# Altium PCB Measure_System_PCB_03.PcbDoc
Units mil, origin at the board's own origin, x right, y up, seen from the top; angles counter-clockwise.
Board outline 6000 x 4000 mil, 2 copper layers (Top Layer, Bottom Layer); 42 components, 34 nets, 113 pads, 0 vias.
Unrouted connection lines stored in the file: 1.
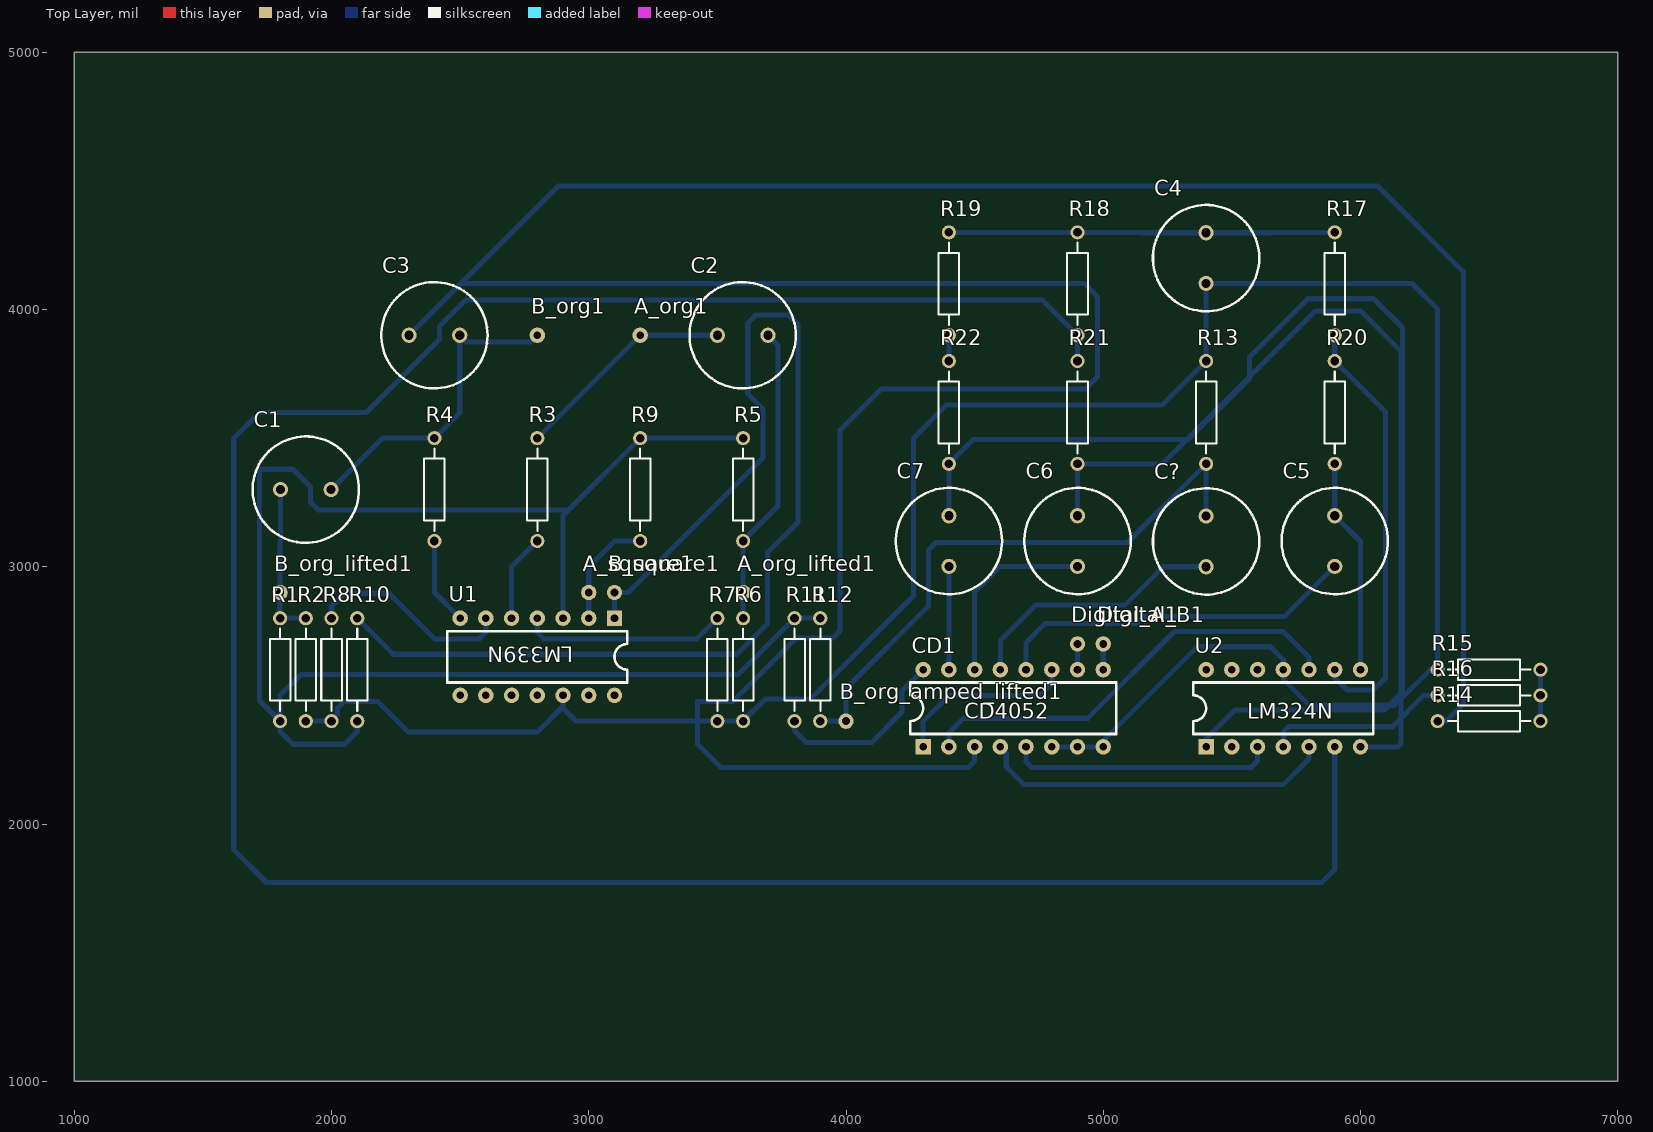
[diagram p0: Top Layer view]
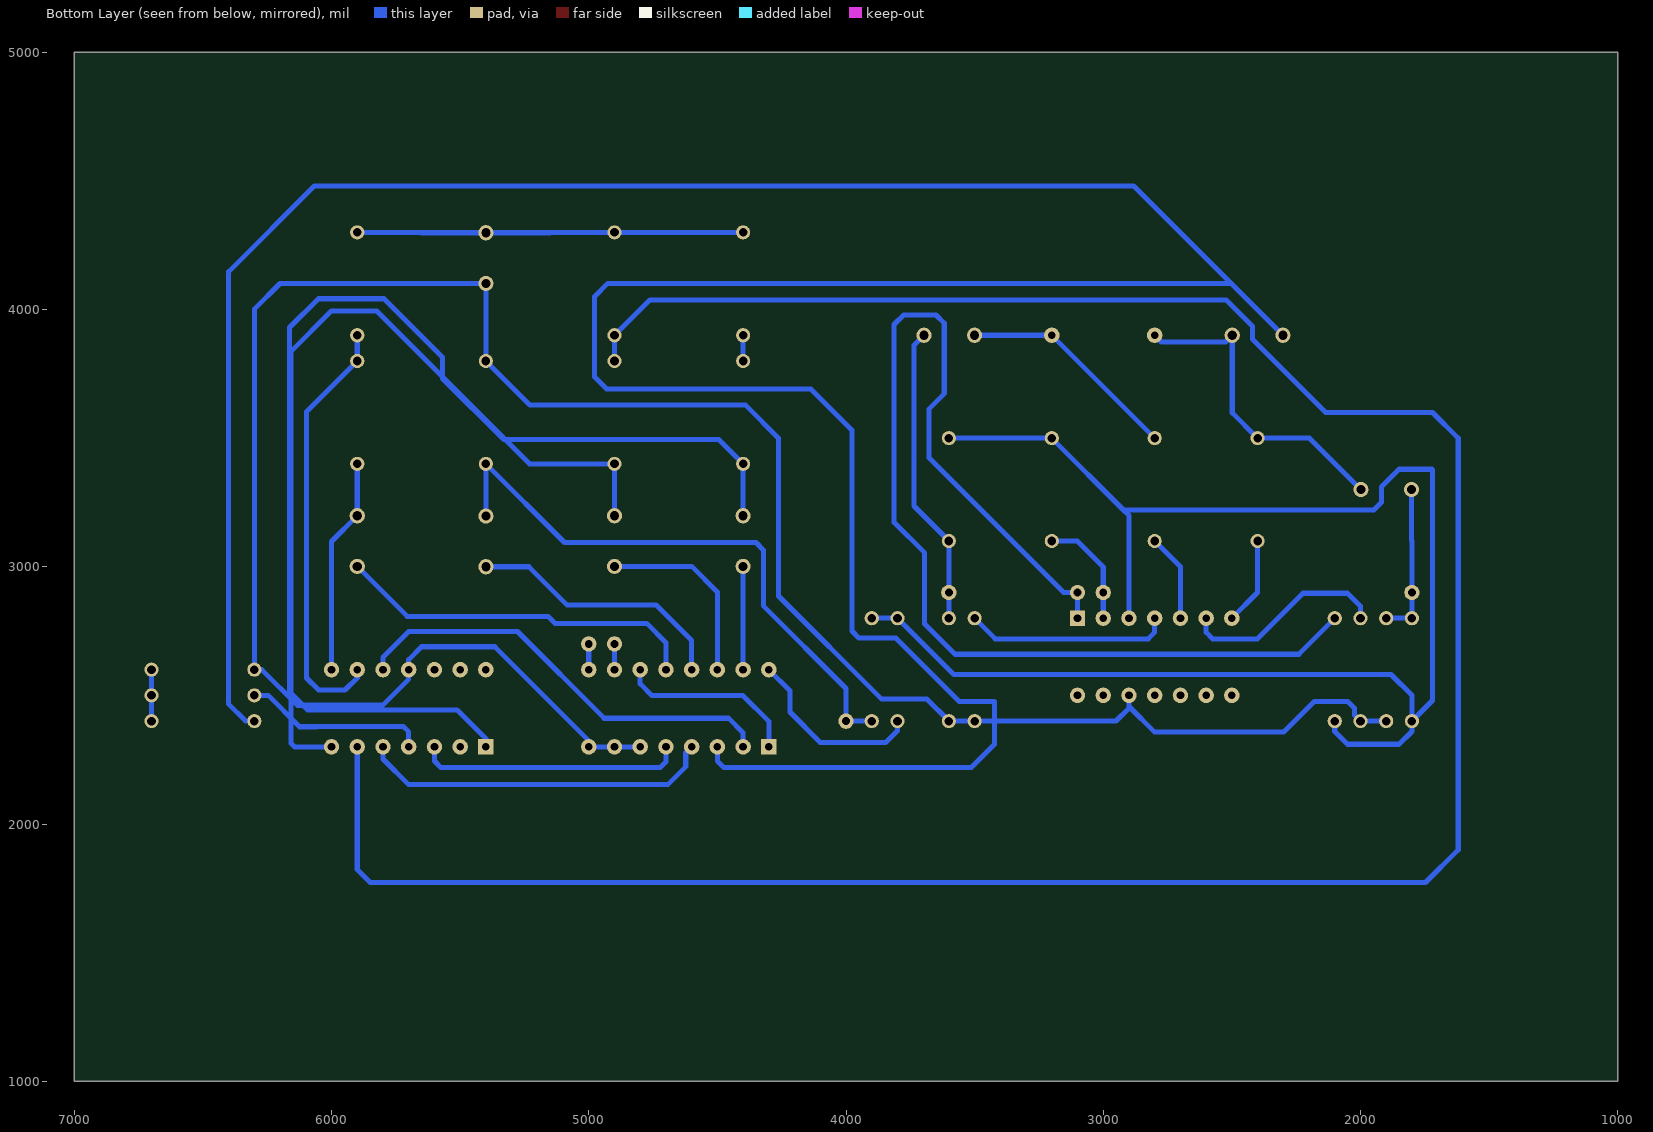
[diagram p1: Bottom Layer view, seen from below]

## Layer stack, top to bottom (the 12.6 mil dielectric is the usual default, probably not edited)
Top Solder: solder mask 0.4, Solder Resist, Dk 3.5
Top Layer: signal copper 1.4
Dielectric 1: dielectric 12.6, FR-4, Dk 4.8
Bottom Layer: signal copper 1.4
Bottom Solder: solder mask 0.4, Solder Resist, Dk 3.5

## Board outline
1000,1000 7000,1000 7000,5000 1000,5000

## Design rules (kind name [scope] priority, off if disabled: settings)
Clearance [All] p1: gap=39.37 ignorepadtopadclearanceinfootprint=FALSE
PolygonConnect [All] p1: connectstyle=Relief reliefconductorwidth=10 reliefentries=4 polygonreliefangle="90 Angle" airgapwidth=10
RoutingLayers [All] p1: top layer_v5=FALSE bottom layer_v5=TRUE
RoutingVias [All] p1: holewidth=28 width=50 viastyle="Through Hole" minholewidth=28 minwidth=50 maxholewidth=28 maxwidth=50
SolderMaskExpansion [All] p1: expansion=4 istentingtop=FALSE
Width [All] p1: maxlimit=393.7 minlimit=19.68 preferedwidth=19.68
29 further rules are at their usual default settings.

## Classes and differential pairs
component class Part_Square: C1 C2 R1 R2 R3 R4 R5 R6 R7 R8 R9 R10 U1
component class Part_PGA: C3 C4 C5 C6 C7 C? CD1 R11 R12 R13 R14 R15 R16 R17 R18 R19 R20 R21 R22 U2
component class Measure_System_Main: A_org1 A_org_lifted1 A_square1 B_org1 B_org_amped_lifted1 B_org_lifted1 B_square1 Digital_A1 Digital_B1

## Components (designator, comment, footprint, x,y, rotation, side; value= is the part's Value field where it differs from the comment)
A_org1 "Hole" Hole 3200,3900 r90 top
A_org_lifted1 "Hole" Hole 3600,2900 r90 top
A_square1 "Hole" Hole 3000,2900 r90 top
B_org1 "Hole" Hole 2800,3900 r90 top
B_org_amped_lifted1 "Hole" Hole 4000,2400 r270 top
B_org_lifted1 "Hole" Hole 1800,2900 r90 top
B_square1 "Hole" Hole 3100,2900 r90 top
C1 "Cap Pol1" RB5-10.5 1900,3300 r180 top value=10u
C2 "Cap Pol1" RB5-10.5 3598.43,3900 r0 top value=10u
C3 "Cap Pol1" RB5-10.5 2400,3900 r180 top value=10u
C4 "Cap Pol1" RB5-10.5 5400,4200 r90 top value=10u
C5 "Cap Pol1" RB5-10.5 5900,3100 r270 top value=10u
C6 "Cap Pol1" RB5-10.5 4900,3100 r270 top value=10u
C7 "Cap Pol1" RB5-10.5 4400,3100 r270 top value=10u
C? "Cap Pol1" RB5-10.5 5400,3098.43 r90 top value=10u
CD1 "CD4052" CD4052 4300,2300 r90 top
Digital_A1 "Hole" Hole 4900,2700 r90 top
Digital_B1 "Hole" Hole 5000,2700 r90 top
R1 "Res2" AXIAL-0.4 1800,2600 r270 top value=100k
R2 "Res2" AXIAL-0.4 1900,2600 r90 top value=100k
R3 "Res2" AXIAL-0.4 2800,3300 r90 top value=1k
R4 "Res2" AXIAL-0.4 2400,3300 r90 top value=1k
R5 "Res2" AXIAL-0.4 3600,3300 r90 top value=100k
R6 "Res2" AXIAL-0.4 3600,2600 r90 top value=100k
R7 "Res2" AXIAL-0.4 3500,2600 r90 top value=10k
R8 "Res2" AXIAL-0.4 2000,2600 r270 top value=10k
R9 "Res2" AXIAL-0.4 3200,3300 r270 top value=10k
R10 "Res2" AXIAL-0.4 2100,2600 r270 top value=10k
R11 "Res2" AXIAL-0.4 3800,2600 r90 top value=200
R12 "Res2" AXIAL-0.4 3900,2600 r90 top value=100k
R13 "Res2" AXIAL-0.4 5400,3600 r270 top value=100k
R14 "Res2" AXIAL-0.4 6500,2400 r180 top value=100k
R15 "Res2" AXIAL-0.4 6500,2600 r0 top value=100k
R16 "Res2" AXIAL-0.4 6500,2500 r0 top value=100k
R17 "Res2" AXIAL-0.4 5900,4100 r270 top value=50k
R18 "Res2" AXIAL-0.4 4900,4100 r270 top value=24k
R19 "Res2" AXIAL-0.4 4400,4100 r270 top value=12k
R20 "Res2" AXIAL-0.4 5900,3600 r270 top value=100k
R21 "Res2" AXIAL-0.4 4900,3600 r270 top value=100k
R22 "Res2" AXIAL-0.4 4400,3600 r270 top value=100k
U1 "LM339N" LM339N 3100,2800 r270 top
U2 "LM324N" LM324N 5400,2300 r90 top

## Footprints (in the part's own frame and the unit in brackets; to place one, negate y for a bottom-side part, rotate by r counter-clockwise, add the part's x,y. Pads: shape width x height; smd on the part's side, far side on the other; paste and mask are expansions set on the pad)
AXIAL-0.4 [mm] "Axial Device, Thru-Hole; 2 Leads; 0.4 in Pin Spacing"
  round 1.4 hole 0.85: 1(-5.08,0) 2(5.08,0)
  silkscreen extent -4.06,-1.02 4.06,1.02
CD4052 [mil]
  rect 60x60 hole 30: 1(0,0)
  round 60 hole 30 mask+4: 2(0,-100) 3(0,-200) 4(0,-300) 5(0,-400) 6(0,-500) 7(0,-600) 8(0,-700) 9(300,-700) 10(300,-600) 11(300,-500) 12(300,-400) 13(300,-300) 14(300,-200) 15(300,-100) 16(300,0)
  silkscreen extent 50,-750 250,50
Hole [mil]
  round 60 hole 30 mask+4: 1(0,0)
LM324N [mil]
  rect 60x60 hole 30: 1(0,0)
  round 60 hole 30 mask+4: 2(0,-100) 3(0,-200) 4(0,-300) 5(0,-400) 6(0,-500) 7(0,-600) 8(300,-600) 9(300,-500) 10(300,-400) 11(300,-300) 12(300,-200) 13(300,-100) 14(300,0)
  silkscreen extent 50,-650 250,50
LM339N [mil]
  rect 60x60 hole 30: 1(0,0)
  round 60 hole 30 mask+4: 2(0,-100) 3(0,-200) 4(0,-300) 5(0,-400) 6(0,-500) 7(0,-600) 8(300,-600) 9(300,-500) 10(300,-400) 11(300,-300) 12(300,-200) 13(300,-100) 14(300,0)
  silkscreen extent 50,-650 250,50
RB5-10.5 [mm] "Capacitor (Radial); 2 Leads"
  round 1.5 hole 0.9: 1(-2.5,0) 2(2.5,0)
  silkscreen extent -5.25,-5.25 5.25,5.25

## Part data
C1 C2 C3 C4 C5 C6 C7 C?: "Polarized Capacitor (Radial)"
R1 R2 R3 R4 R5 R6 R7 R8 R9 R10 R11 R12 R13 R14 R15 R16 R17 R18 R19 R20 R21 R22: "Resistor"

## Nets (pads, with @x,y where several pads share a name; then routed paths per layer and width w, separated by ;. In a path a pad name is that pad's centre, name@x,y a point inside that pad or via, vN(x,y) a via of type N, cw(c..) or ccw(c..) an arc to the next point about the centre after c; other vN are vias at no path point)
+5: R1.2 R5.2 R9.1 R10.2 R11.2 R12.2 U1.3 | length 6281.9
  Bottom Layer w19.68: R10.2 2100,2360 2050,2310 1850,2310 1800,2360 R1.2 ; U1.3 2900,3200 2921,3221 ; R5.2 R9.1 2921,3221 ; R12.2 R11.2 3580.95,2580.95 1880.95,2580.95 1800,2500 R1.2 ; R1.2 1720,2480 1720,3376 1723,3379 1850,3379 1919,3310 1919,3250 1948,3221 2921,3221
+12: R16.1 U2.4 | length 717.9
  Bottom Layer w19.68: U2.4 5700,2358.21 5721,2379.21 6056.79,2379.21 6058,2378 6124.52,2378 6246.52,2500 R16.1
B_org: B_org1.1 C1.1 C3.1 R4.2 | length 1248.7
  Bottom Layer w19.68: C1.1 2198.43,3500 R4.2 2498.43,3598.43 C3.1 2524.87,3873.56 2773.56,3873.56 B_org1.1
B_org_amp_1: CD1.1 CD1.11 | length 714.5
  Bottom Layer w19.68: CD1.1 4300,2399 4400,2499 4754,2499 4800,2545 CD1.11
B_org_amp_2.5: C5.2 CD1.12 | length 1427.8
  Bottom Layer w19.68: CD1.12 4700,2705 4775,2780 5131.26,2780 5158.38,2807.11 5705.54,2807.11 C5.2
B_org_amp_5: C6.2 CD1.14 | length 743
  Bottom Layer w19.68: CD1.14 4500,2901.57 4600,3001.57 C6.2
B_org_amp_10: C7.2 CD1.15 | length 401.6
  Bottom Layer w19.68: CD1.15 C7.2
B_org_amped: C?.1 CD1.13 | length 1031.9
  Bottom Layer w19.68: CD1.13 4600,2713 4739,2852 5085.15,2852 5233.15,3000 C?.1
B_org_to_amp: C3.2 CD1.3 R14.2 | length 12973.8
  Bottom Layer w19.68: C3.2 2503.57,4102 ; CD1.3 4500,2245 4475,2220 3513,2220 3423,2310 3423,2477 3560.52,2477 3806.52,2723 3950,2723 3977,2750 3977,3531 4137,3691 4930,3691 4977,3738 4977,4051 4926,4102 2503.57,4102 ; R14.2 6334,2400 6400,2466 6400,4147 6066,4481 2882.57,4481 2503.57,4102
B_org_to_amp_2.5: CD1.2 U2.10 | length 1707.3
  Bottom Layer w19.68: CD1.2 4400,2355 4456,2411 4940.21,2411 5277.27,2748.06 5700,2748.06 5800,2648.06 U2.10
B_org_to_amp_5: CD1.4 U2.5 | length 1380.9
  Bottom Layer w19.68: CD1.4 4622.96,2277.04 4622.96,2223.04 4693,2153 5700,2153 5800,2253 U2.5
B_org_to_amp_10: CD1.5 U2.3 | length 1032.5
  Bottom Layer w19.68: CD1.5 4700,2242 4722,2220 5575,2220 5600,2245 U2.3
Digital_A: CD1.10 Digital_A1.1 | length 100
  Bottom Layer w19.68: CD1.10 Digital_A1.1
Digital_B: CD1.9 Digital_B1.1 | length 100
  Bottom Layer w19.68: CD1.9 Digital_B1.1
GND: C4.1 CD1.6 CD1.7 CD1.8 R2.1 R6.1 R7.1 R8.2 R13.1 R15.1 U1.12 U2.11 | length 9174.1
  Bottom Layer w19.68: R2.1 R8.2 2023,2423 2023,2450 2050,2477 2179,2477 2299,2357 2800,2357 2900,2457 ; U1.12 2900,2457 ; CD1.6 CD1.7 CD1.8@4976.54,2300 ; CD1.8 CD1.8@4976.54,2300 ; 2900,2457 2900,2450 2950,2400 R7.1 R6.1 3685.23,2485.23 3861.23,2485.23 4262.2,2886.2 4262.2,3500 4390.23,3628.03 5228.03,3628.03 R13.1 C4.1 6200,4101.57 6300,4001.57 R15.1 6271,2600 6132.73,2461.73 5801.27,2461.73 5700,2563 U2.11 5700,2639 5650,2689 5365.54,2689 CD1.8@4976.54,2300
NetA_org1_1: A_org1.1 C2.1 R3.2 | length 865.7
  Bottom Layer w19.68: R3.2 3007.23,3707.22 ; 3007.23,3707.23 A_org1.1 C2.1
NetA_org_lifted1_1: A_org_lifted1.1 C2.2 R5.1 R6.2 | length 1172.4
  Bottom Layer w19.68: R6.2 3600,2849 A_org_lifted1.1 3600,2999 R5.1 3735.83,3235.83 3735.83,3861.02 C2.2
NetA_square1_1: A_square1.1 R9.2 U1.2 | length 440.8
  Bottom Layer w19.68: U1.2 A_square1.1 3000,2999 3101,3100 R9.2
NetB_org_amped_lifted1_1: B_org_amped_lifted1.1 C?.2 R12.1 R13.2 | length 2318.9
  Bottom Layer w19.68: R12.1 B_org_amped_lifted1.1 4000,2526.74 4321.26,2848 4321.26,3065.26 4350,3094 5094,3094 R13.2 C?.2
NetB_org_lifted1_1: B_org_lifted1.1 C1.2 R1.1 R2.2 | length 600.7
  Bottom Layer w19.68: C1.2 1801.58,3101.58 1800,3100 B_org_lifted1.1 R1.1 R2.2
NetB_square1_1: B_square1.1 R10.1 U1.1 | length 4579.4
  Bottom Layer w19.68: R10.1 2240,2660 3576.48,2660 3694,2777.52 3694,3054 3813,3173 3813,3941.74 3776,3978.74 3649.74,3978.74 3618,3947 3618,3672.77 3676.77,3614 3676.77,3423 3153.77,2900 B_square1.1 U1.1
NetC4_2: C4.2 R17.1 R18.1 R19.1 | length 1501.3
  Bottom Layer w19.68: R19.1 R18.1 5150,4300 5151.57,4298.43 C4.2 5650,4298.43 5651.57,4300 R17.1
NetC5_1: C5.1 R20.2 U2.8 | length 841.4
  Bottom Layer w19.68: R20.2 C5.1 6000,3098.43 U2.8
NetC6_1: C6.1 R21.2 U2.7 | length 3457.4
  Bottom Layer w19.68: C6.1 R21.2 5230,3400 5825,3995 6000,3995 6157,3838 6157,2313 6144,2300 U2.7
NetC7_1: C7.1 R22.2 U2.1 | length 4611.6
  Bottom Layer w19.68: C7.1 R22.2 4494.12,3494.12 5330.34,3494.12 5568.19,3731.97 5568.19,3814.19 5796,4042 6051,4042 6163,3930 6163,2513.65 6093.35,2444 5512,2444 5400,2332 U2.1
NetCD1_16: CD1.16 R11.1 | length 721.9
  Bottom Layer w19.68: R11.1 3800,2363 3846,2317 4100,2317 4218,2435 4218,2518 CD1.16
NetR3_1: R3.1 U1.5 | length 341.4
  Bottom Layer w19.68: U1.5 2700,3000 R3.1
NetR4_1: R4.1 U1.7 | length 341.4
  Bottom Layer w19.68: R4.1 2400,2900 U1.7
NetR7_2: R7.2 U1.4 | length 798.5
  Bottom Layer w19.68: U1.4 2800,2745 2825,2720 3420,2720 R7.2
NetR8_1: R8.1 U1.6 | length 806.4
  Bottom Layer w19.68: R8.1 2000,2847 2050,2897 2223,2897 2400,2720 2575,2720 2600,2745 U1.6
NetR14_1: R14.1 R15.2 R16.2 | length 200
  Bottom Layer w19.68: R14.1 R16.2 R15.2
NetR17_2: R17.2 R20.1 U2.9 | length 1681.8
  Bottom Layer w19.68: U2.9 5900,2568 5947.21,2520.79 6050,2520.79 6097,2567.79 6097,3603 R20.1 R17.2
NetR18_2: R18.2 R21.1 U2.6 | length 10119.4
  Bottom Layer w19.68: R21.1 R18.2 4762.2,4037.8 2522.89,4037.8 2419.68,3934.59 2419.68,3884.68 2135,3600 1720,3600 1620,3500 1620,1900 1747,1773 5850,1773 5900,1823 U2.6
NetR19_2: R19.2 R22.1 U2.2 | length 100
  Bottom Layer w19.68: R22.1 R19.2
pads on no net: U1.8 U1.9 U1.10 U1.11 U1.13 U1.14 U2.12 U2.13 U2.14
